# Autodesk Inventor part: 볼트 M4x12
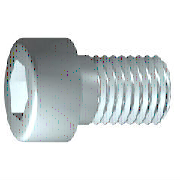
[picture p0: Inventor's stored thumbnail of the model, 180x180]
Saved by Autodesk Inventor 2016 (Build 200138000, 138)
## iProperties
IsCustomPart: 0
Created: 2012-02
Part Number: 볼트 M4x12
Material: 강철, 연강
Description: 6각머리 태핑 나사
Document SubType Name: Modeling
Standard: KS B 1003
Designer: mduedu
Standards Organization: KS
Language: ko-KR
Size Designation: M 4 x 12
Categories: <MemberInstance><Categories><Category DisplayName="조임쇠" InternalName="e4da775c-781d-43d5-af7c-5136215cf5a6" Mnemonic="FSTN"><Category DisplayName="볼트" InternalN
Density: 1 g/cm^3
Appearance: 강철
Author: mduedu
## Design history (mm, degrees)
sketch "스케치1"
  geometry: L1 (-1, 0)-(12, 0); L2 (12, 0)-(12, 2); L3 (12, 2)-(1.75, 2); L4 (1.75, 2)-(1.32, 2); L5 (1.32, 2)-(0, 2); L6 (0, 2)-(0, 3.5); L7 (0, 3.5)-(-4, 3.5); L8 (-4, 3.5)-(-4, 1.732); L9 (-4, 1.732)-(-2, 1.732); L10 (-2, 1.732)-(-1, 0); L11 (-7.2, 0)-(15.2, 0) reference; L12 (0, -0.7)-(0, 4.2) reference; L13 (1.75, 2)-(0, 2)
  constraints: 22 end point, 6 parallel, 2 collinear, 2 perpendicular, 1 horizontal, 1 point on line
  dimensions: "d1" = 10.25 distance from line of L3.end L2 (= GEL); "d2" = 0.42952 distance of L4.end L3.end (computed from GAL); "d3" = 4 distance between parallel lines of L8 L6 (= KOH); "d4" = 2 distance of L8.end L9.end (= INTI); "d5" = 60 deg angle of L10 L1; "d6" = 4 diameter of L3 L1 (= GD); "d7" = 4 diameter of L5 L1 (= BDM); "d8" = 3.4641 diameter of L9 L1 (= 1.1547 x SW); "d9" = 7 diameter of L7 L1 (= KOD); "d26" = 12 distance between parallel lines of L12 L2 (= NLG)
revolve "본체" sketch "스케치1" stored, may be unused: angle "d10" = 90 deg
sketch "스케치2"
  geometry: L1 (0, -4.9)-(0, 4.9) reference; L2 (-4.9, 0)-(4.9, 0) reference; L3 (1.732, 0)-(0.866, -1.5); L4 (0.866, -1.5)-(-0.866, -1.5); L5 (-0.866, -1.5)-(-1.732, 0); L6 (-1.732, 0)-(-0.866, 1.5); L7 (-0.866, 1.5)-(0.866, 1.5); L8 (0.866, 1.5)-(1.732, 0); 2 further points
  constraints: 12 end point, 1 coincident, 1 horizontal alignment, 1 point on line, 12 other
extrude "슬롯" join sketch "스케치2" stored distance "d11" = 10; taper "d12" = 0 deg
workplane "Work Plane1"
fillet "Fillet2" dims "d30" = 0.1 (= R)
body "Solid1"
fillet "모깎기1" dims "d17" = 0.4 (= RR)
feature "스레드" dims "d13" = 10.25 (= GEL), "d14" = 0
chamfer "모따기1" distance "d15" = 0.42941 (= -0.5 x SPD + 0.5 x GD); stored, may be unused: second distance "d16" = 0.42941 (= GUL), angle "d27" = 45 deg
other parameters: "GD" = 4 (= NND) [user parameter; used in 2 equation terms], "NLG" = 12 [user parameter; used in 1 equation term], "GEL" = 10.25 [user parameter; used in 2 equation terms], "KOD" = 7 [user parameter; used in 1 equation term], "KOH" = 4 [user parameter; used in 1 equation term], "INTI" = 2 [user parameter; used in 1 equation term], "GAL" = 0.42941 (= 0.61345 x PTC) [user parameter; used in 1 equation term], "GUL" = 0.42941 (= 0.61345 x PTC) [user parameter; used in 1 equation term], "BDM" = 4 (= NND) [user parameter; used in 1 equation term], "SW" = 3 [user parameter; used in 2 equation terms], "RR" = 0.4 [user parameter; used in 1 equation term], "SPD" = 3.14117 (= NND - 1.2269 x PTC) [user parameter; used in 1 equation term], "d19" = 0, "d28" = 0, "d29" = 0, "R" = 0.1 [user parameter; used in 1 equation term], "PHH" = 0.2 [user parameter], "GD1" = 3.14117 (= THREADDIA - 1.2269 x PTC) [user parameter], "THREADDIA" = 4 [user parameter; used in 1 equation term], "FAWI" = 45 deg [user parameter], "TPU" = 14.28571 (computed from PTC) [user parameter], "PTC" = 0.7 [user parameter; used in 5 equation terms], "NND" = 4 [user parameter; used in 3 equation terms], "TOA" = 30 deg [user parameter], "E0" = 3.465 (= 1.155 x SW) [user parameter]
